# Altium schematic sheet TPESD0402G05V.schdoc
size 127 x 101 mm
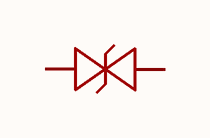
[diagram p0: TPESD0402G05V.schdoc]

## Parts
D?  tpesd0402g05v  [D0402-BI]  (value not drawn)

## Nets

Not connected (* = marked no-connect by the designer): D? 1(K) 2(A)

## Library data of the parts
D? = tpesd0402g05v: 极性:双向;反向截止电压(Vrwm):5V;最大钳位电压:40V;峰值脉冲电流(Ipp):-;峰值脉冲功率(Ppp):-;击穿电压:-;; Manufacturer: TECH PUBLIC(台舟); AddInBom: yes; ModelId: 62a80a189f1b46df8ba79817b730b378; ModelName: D0402_L1.0-W0.5-H0.5; ModelTransform: 39.37,19.685,0,0,0,0,0,0,0; polarity: 双向; Reverse Stand-Off Voltage (Vrwm): 5V; Maximum Clamping Voltage: 40V; Reverse Leakage Current (Ir): 10nA; Number of Lines: 单路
